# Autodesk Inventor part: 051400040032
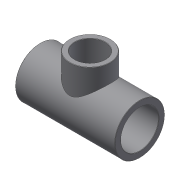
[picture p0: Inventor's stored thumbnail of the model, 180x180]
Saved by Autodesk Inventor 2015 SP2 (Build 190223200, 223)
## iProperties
Created: 2017-10
Part Number: 051400040032
Material: Generic
Description: PLASSON REDUCER TEE - CEMENT PVC 40-32-40
Document SubType Name: Modeling
Designer: KIM
Density: 1 g/cm^3
Appearance: Default
Author: KIM
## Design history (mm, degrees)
derived "051400.ipt"
feature "Solid1::051400.ipt"
feature "Solid2::051400.ipt"
tag "TaggingFeature1"
body "Solid1"
other parameters: "d0" = 99, "d2" = 26, "d5" = 36, "d7" = 0.4, "d8" = 26, "d9" = 47, "d10" = 44, "d11" = 32, "d12" = 28.8, "d23" = 22, "d24" = 0.4, "d26" = 0, "d30" = 0, "d32" = 0, "H_" = 99, "l_" = 26, "Z_" = 14, "E_1" = 44, "l_1" = 22, "Z_1" = 12.5, "H_1" = 72, "d_1" = 32
